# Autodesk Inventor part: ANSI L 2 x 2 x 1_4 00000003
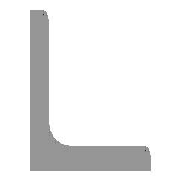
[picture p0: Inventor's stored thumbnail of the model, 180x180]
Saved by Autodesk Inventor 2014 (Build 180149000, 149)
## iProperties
_FrameMemberDoc: Frame Member File
_Version: 15.0.0
_CCFamilyMember: 11
_CCFamilyDisplayName: ANSI L (Equal angles) - Angle Steel
Created: 2007-02
Part Number: ANSI L 2 x 2 x 1_4 00000003
Material: Steel, Mild
Document SubType Name: Modeling
Standard: AISC
Designer: Autodesk, Inc.
Size Designation: L 2 x 2 x 1/4
Stock Number: L 2 x 2 x 1/4
Density: 7.86 g/cm^3
Description: Angle Steel
Standards Organization: ANSI
Language: en-US
Categories: <MemberInstance><Categories><Category DisplayName="Structural Shapes" InternalName="089c4875-fa83-4c05-b084-43b9cc11f5ed" Mnemonic="GRDR"><CategoryParameter Dis
Mass: 4968.52 g
Surface Area: 2066.09 cm^2
Volume: 632.127 cm^3
Appearance: Steel
IsCustomPart: 1
G_L: 42.000 in
G_W: 2.000 in
G_H: 2.000 in
+83905929-4DA7-493A-BC2A-CF29B1304FE5+CUTDETAIL1: Miter 45.00 deg
+DBC74A79-B4E1-4546-89DD-9F49D268AF4C+CUTDETAIL2: Miter 45.00 deg
Author: Autodesk, Inc.
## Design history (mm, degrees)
node "Start plane"
node "End plane"
sketch "Sketch"
  geometry: L1 (50.8, 0)-(0, 0); L2 (0, 0)-(0, 50.8); L3 (0, 50.8)-(3.302, 50.8); L4 (6.35, 47.752)-(6.35, 12.7); L5 (12.7, 6.35)-(47.752, 6.35); L6 (50.8, 3.302)-(50.8, 0); L7 (0, -11.041)-(0, 31.538); L8 (-11.041, 0)-(31.538, 0); L9 (0, 63.926)-(0, -23.536) reference; L10 (-23.536, 0)-(63.926, 0) reference; A1 r 6.35 centre (12.7, 12.7) between (6.35, 12.7) and (12.7, 6.35); A2 r 3.048 centre (3.302, 47.752) between (6.35, 47.752) and (3.302, 50.8); A3 r 3.048 centre (47.752, 3.302) between (50.8, 3.302) and (47.752, 6.35); 3 further points
  constraints: 16 end point, 6 point on circle, 6 point on line, 6 tangent, 4 parallel, 3 centre point, 2 collinear, 1 equal radius, 1 horizontal, 1 perpendicular
  dimensions: "d0" = 50.8 distance between parallel lines of L6 L2 (= G_H); "d1" = 50.8 distance between parallel lines of L3 L1 (= G_H); "d2" = 6.35 distance between parallel lines of L2 L4 (= G_T); "d3" = 6.35 distance between parallel lines of L1 L5 (= G_T); "d10" = 0 distance between parallel lines of L7 L2 (computed from ex); "d11" = 0 distance between parallel lines of L8 L1 (computed from d10); "d14" = 6.35 radius of A1 (= G_IR); "d15" = 3.048 radius of A2 (= G_ER)
extrude "Body" new body sketch "Sketch" stored distance "d4" = 1066.8 (= G_L); taper "d5" = 0 deg
node "Driven Length"
  sketch "Sketch3"
    geometry: L1 (0, 0)-(10, 0) reference
    constraints: 2 end point, 1 horizontal
  workplane "Work Plane5"
  sketch "Sketch4"
    geometry: L1 (-2, -6.35)-(12, -6.35) reference; L2 (-2, 1060.45)-(12, 1060.45) reference
    dimensions: "d17" = 1066.8 distance between parallel lines of L1 L2 (derived)
workplane "Work Plane3"
split "Split1"
workplane "Work Plane4"
split "Split2"
body "Solid1"
other parameters: "G_H" = 50.8 [user parameter; used in 2 equation terms], "G_T" = 6.35 [user parameter; used in 2 equation terms], "G_ER" = 3.048 [user parameter; used in 1 equation term], "G_IR" = 6.35 [user parameter; used in 1 equation term], "G_L" = 1066.8 (= d17) [user parameter; used in 1 equation term], "ex" = 0 [user parameter; used in 1 equation term], "G_OFFSET_START" = 6.35 [user parameter; used in 1 equation term], "G_OFFSET_END" = 6.35 [user parameter; used in 1 equation term], "d12" = -6.35 (= -G_OFFSET_START), "d13" = 1060.45 (= G_OFFSET_END + B_L), "B_L" = 1054.1 [user parameter; used in 1 equation term], "d16" = 90 deg
